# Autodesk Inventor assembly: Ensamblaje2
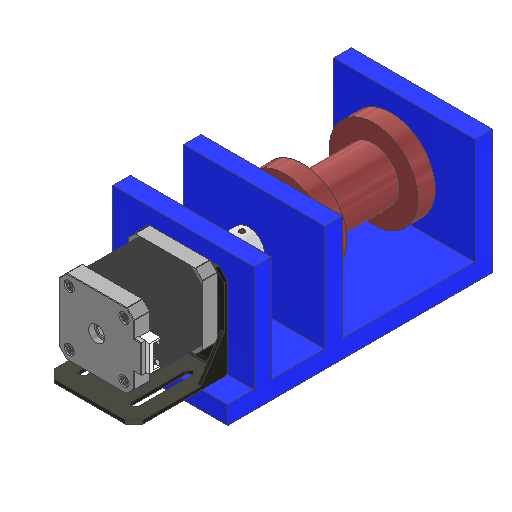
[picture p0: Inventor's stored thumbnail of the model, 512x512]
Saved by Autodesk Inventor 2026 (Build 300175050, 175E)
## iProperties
Created: 2025-06
Part Number: Ensamblaje2
Document SubType Name: Assembly
Designer: piero
Author: piero
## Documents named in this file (11)
- C:\Users\piero\OneDrive\Documentos\UTEC\Ciclo 2025-1\PFC_1\ModeloBase\Ensamblaje2.iam
- C:\Users\piero\OneDrive\Documentos\UTEC\Ciclo 2025-1\PFC_1\ModeloBase\soporte_inferior.ipt
- C:\Users\piero\OneDrive\Documentos\UTEC\Ciclo 2025-1\PFC_1\ModeloBase\carrete.ipt
- C:\Users\piero\OneDrive\Documentos\UTEC\Ciclo 2025-1\PFC_1\ModeloBase\acople_suave.ipt
- C:\Users\piero\OneDrive\Documentos\UTEC\Ciclo 2025-1\PFC_1\ModeloBase\Stepper Motor Nema 17_.ipt
- C:\Users\piero\OneDrive\Documentos\UTEC\Ciclo 2025-1\PFC_1\ModeloBase\perno_pasante.ipt
- C:\Users\piero\OneDrive\Documentos\UTEC\Ciclo 2025-1\PFC_1\ModeloBase\Soporte_NEMA17.ipt
- C:\Users\piero\OneDrive\Documentos\Inventor\Content Center Files\R2026\es-ES\BS EN ISO 7046-2 H\BS EN ISO 7046-2 H - M3x20 - 8.8 - H1.ipt
- C:\Users\piero\OneDrive\Documentos\UTEC\Ciclo 2025-1\PFC_1\ModeloBase\Roda-608\w_608-2rs1.iam
- C:\Users\piero\OneDrive\Documentos\UTEC\Ciclo 2025-1\PFC_1\ModeloBase\Brida1.ipt
- C:\Users\piero\OneDrive\Documentos\Inventor\Content Center Files\R2026\es-ES\AS 1421(4)\AS 1421 - M3 x 4 Punta plana.ipt
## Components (23 placed, 10 different names)
1. soporte_inferior:1 — Coincidencia:5, Coincidencia:8, De rotación:1
2. carrete:1 — Coincidencia:7, Coincidencia:17, Coincidencia:18, Coincidencia:19, Coincidencia:20, Coincidencia:21, Coincidencia:22
3. acople_suave:2 — Coincidencia:6, Coincidencia:16
4. Stepper Motor Nema 17_:2 — Coincidencia:8
5. perno_pasante:1 — Coincidencia:5, Coincidencia:6, Coincidencia:7, Coincidencia:13, Coincidencia:14, Coincidencia:15
6. Soporte_NEMA17:1
7. BS EN ISO 7046-2 H M3x20 - 8.8 - H1:1
8. BS EN ISO 7046-2 H M3x20 - 8.8 - H1:2
9. BS EN ISO 7046-2 H M3x20 - 8.8 - H1:3
10. BS EN ISO 7046-2 H M3x20 - 8.8 - H1:4
11. w_608-2rs1:1 [sub-assembly] — Coincidencia:13, De rotación:1
12. Brida1:1 — Coincidencia:14
13. Brida1:2 — Coincidencia:15
14. AS 1421 Punta plana - Métrico M3 x 4 Punta plana:1
15. AS 1421 Punta plana - Métrico M3 x 4 Punta plana:3
16. AS 1421 Punta plana - Métrico M3 x 4 Punta plana:4
17. AS 1421 Punta plana - Métrico M3 x 4 Punta plana:5 — Coincidencia:16
18. AS 1421 Punta plana - Métrico M3 x 4 Punta plana:6 — Coincidencia:18
19. AS 1421 Punta plana - Métrico M3 x 4 Punta plana:7 — Coincidencia:19
20. AS 1421 Punta plana - Métrico M3 x 4 Punta plana:8 — Coincidencia:17
21. AS 1421 Punta plana - Métrico M3 x 4 Punta plana:9 — Coincidencia:21
22. AS 1421 Punta plana - Métrico M3 x 4 Punta plana:10 — Coincidencia:20
23. AS 1421 Punta plana - Métrico M3 x 4 Punta plana:11 — Coincidencia:22
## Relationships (15: Mate 14, RevoluteJoint 1)
- Coincidencia:5 [Mate]: soporte_inferior:1 ↔ perno_pasante:1
- Coincidencia:6 [Mate]: acople_suave:2 ↔ perno_pasante:1
- Coincidencia:7 [Mate]: carrete:1 ↔ perno_pasante:1
- Coincidencia:8 [Mate]: soporte_inferior:1 ↔ Stepper Motor Nema 17_:2
- Coincidencia:13 [Mate]: perno_pasante:1 ↔ w_608-2rs1:1
- Coincidencia:14 [Mate]: perno_pasante:1 ↔ Brida1:1
- Coincidencia:15 [Mate]: perno_pasante:1 ↔ Brida1:2
- De rotación:1 [RevoluteJoint]: soporte_inferior:1 ↔ w_608-2rs1:1
- Coincidencia:16 [Mate]: acople_suave:2 ↔ AS 1421 Punta plana - Métrico M3 x 4 Punta plana:5
- Coincidencia:17 [Mate]: carrete:1 ↔ AS 1421 Punta plana - Métrico M3 x 4 Punta plana:8
- Coincidencia:18 [Mate]: carrete:1 ↔ AS 1421 Punta plana - Métrico M3 x 4 Punta plana:6
- Coincidencia:19 [Mate]: carrete:1 ↔ AS 1421 Punta plana - Métrico M3 x 4 Punta plana:7
- Coincidencia:20 [Mate]: carrete:1 ↔ AS 1421 Punta plana - Métrico M3 x 4 Punta plana:10
- Coincidencia:21 [Mate]: carrete:1 ↔ AS 1421 Punta plana - Métrico M3 x 4 Punta plana:9
- Coincidencia:22 [Mate]: carrete:1 ↔ AS 1421 Punta plana - Métrico M3 x 4 Punta plana:11
